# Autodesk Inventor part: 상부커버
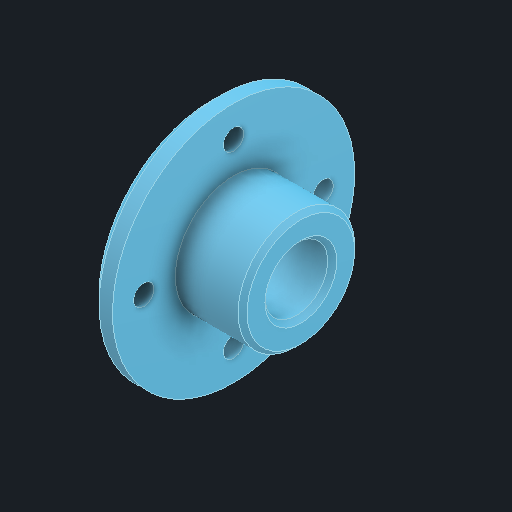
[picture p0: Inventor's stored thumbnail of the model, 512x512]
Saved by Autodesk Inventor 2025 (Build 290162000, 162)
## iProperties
Created: 2025-08
Part Number: 상부커버
Material: 알루미늄 6061
Document SubType Name: Modeling
Designer: infra012
Density: 2.71 g/cm^3
Appearance: 기본값
Author: jhkim
Sending System: Autodesk Inventor 2026
Preprocessor: ST-DEVELOPER v20.1
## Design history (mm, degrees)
sketch "스케치1"
  geometry: 1 further point
  constraints: 1 other
feature "솔리드1"
node "솔리드2"
